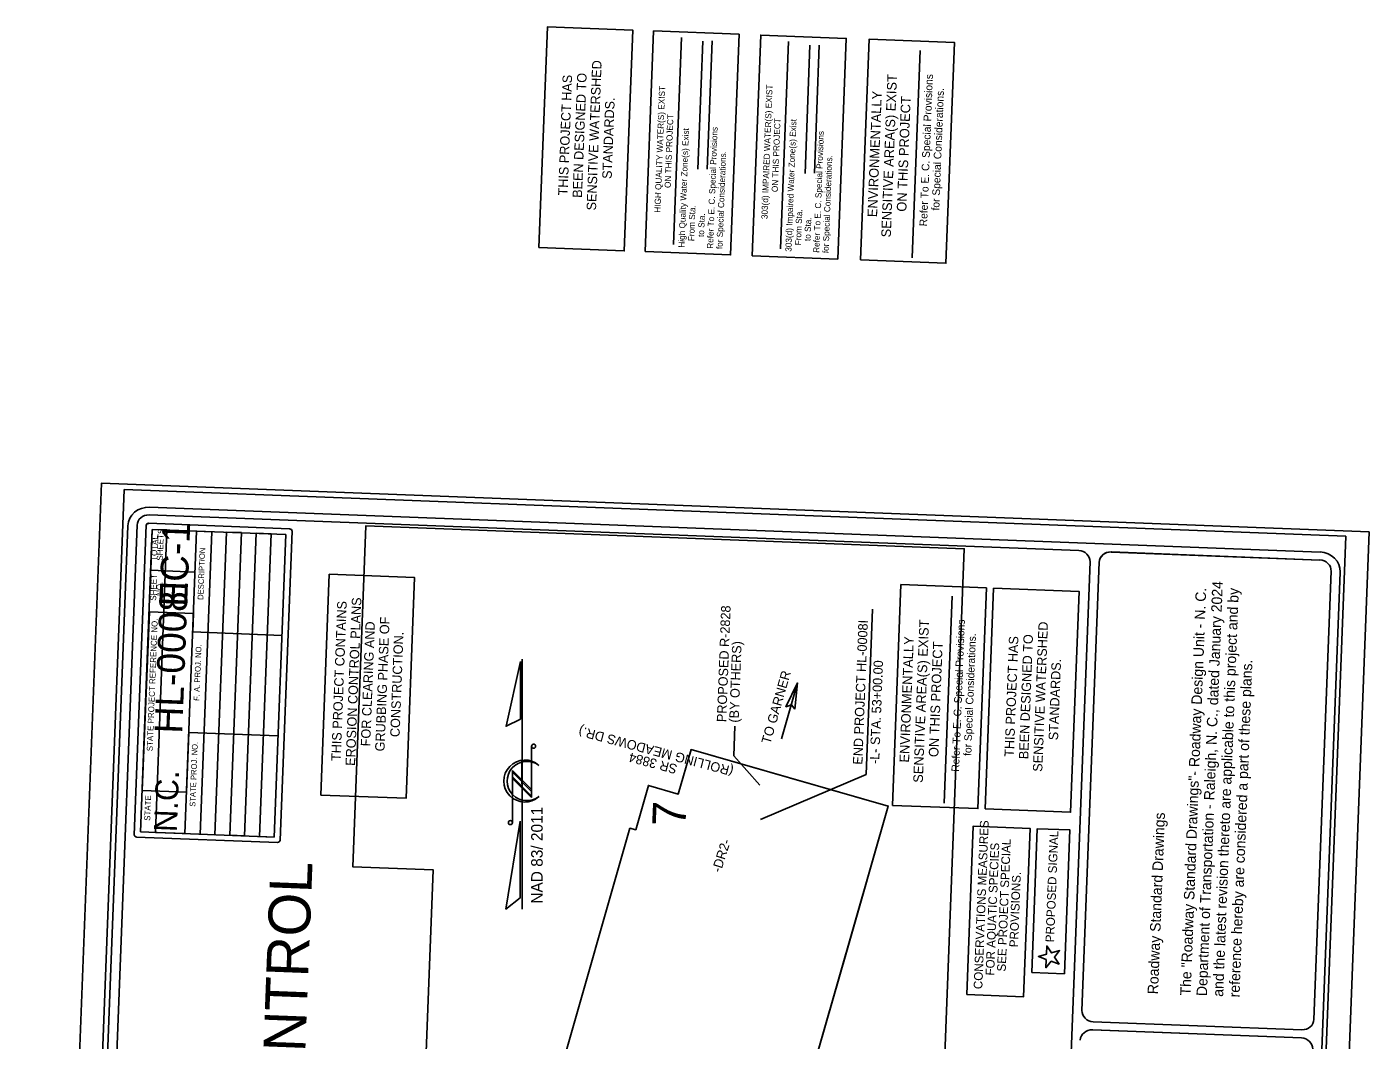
# Model space of a CAD drawing. Extents: x 1654773 to 2116434, y 680831 to 888488.
# Drawn here: x 2094746 to 2100565, y 688306 to 692697 of the extents above; entities that cross this region are included whole.
import ezdxf

# ---------------------------------------------------------------- set-up
doc = ezdxf.new("R2010")
doc.units = 0
for name, color, linetype in [('Default', 7, 'Continuous'), ('EC Title Sheet CELL', 7, 'Continuous'), ('EC Title Sheet Consultant CELL', 7, 'Continuous'), ('Prop DSN Text', 7, 'Continuous'), ('Prop Horizontal Alignment', 7, 'Continuous'), ('Prop RDY Traffic Signal CELL', 7, 'Continuous'), ('Prop Terminator CELL', 7, 'Continuous'), ('Scratch_Level_3', 7, 'Continuous'), ('Sheet Data Field CELL', 7, 'Continuous'), ('Sheet North Arrow CELL', 7, 'Continuous'), ('Sheet Plot Border Inside CELL', 7, 'Continuous'), ('Sheet Plot Border Outside CELL', 7, 'Continuous'), ('Sheet Title CELL', 7, 'Continuous')]:
    doc.layers.add(name, color=color, linetype=linetype)

msp = doc.modelspace()

# ---------------------------------------------------------------- linework, layer by layer
at = {"layer": 'Default'}
msp.add_line((2096893.9, 689316.6), (2096892.4, 689515), dxfattribs=at)
at = {"layer": 'EC Title Sheet CELL'}
for p, q in [((2097655.6, 692079.9), (2097676.9, 692635.1)), ((2097695.7, 692080.9), (2097717, 692636.1)), ((2098119.9, 692062.1), (2098141.2, 692617.3)), ((2098160, 692063.1), (2098181.4, 692618.2)), ((2095069.1, 690719.1), (2095069.1, 690719.1)), ((2095168.6, 690692.8), (2095168.6, 690692.8)), ((2100352.6, 690421), (2095278.4, 690615.8)), ((2095276, 690582.2), (2099306.4, 690427.5)), ((2094948.2, 683360.1), (2095223.7, 690537.4)), ((2095263.2, 690536.9), (2095211.7, 689195.8)), ((2095289.8, 690519), (2095239.5, 689207.9)), ((2095885.3, 690521.8), (2095273.6, 690545.8)), ((2095289.8, 690519), (2095284.1, 690342.6)), ((2095353.6, 690516.7), (2095289.8, 690519)), ((2095868.9, 690496.8), (2095289.8, 690519)), ((2095303.2, 689206.3), (2095353.6, 690516.7)), ((2095481.8, 690511.8), (2095431.5, 689201.4)), ((2095547.5, 690509.3), (2095481.8, 690511.8)), ((2095497.3, 689198.9), (2095547.5, 690509.3)), ((2095611.2, 690506.7), (2095560.9, 689195.5)), ((2095676.9, 690505.1), (2095611.2, 690506.7)), ((2095626.6, 689194), (2095676.9, 690505.1)), ((2095739.6, 690502.8), (2095689.3, 689191.5)), ((2095805.3, 690500.2), (2095739.6, 690502.8)), ((2095754.9, 689189), (2095805.3, 690500.2)), ((2095868.9, 690496.8), (2095818.6, 689185.6)), ((2095843.8, 689172.5), (2095896.1, 690511)), ((2099079.7, 683201.5), (2099355.1, 690378.9)), ((2099320, 688434.4), (2099394.5, 690377.3)), ((2099446.8, 690421.1), (2100351.4, 690386.4)), ((2099448.9, 690422), (2100351.4, 690386.4)), ((2095284.1, 690342.6), (2095475.1, 690334.3)), ((2100400, 690337.9), (2100325.5, 688395.8)), ((2095246.5, 689387.9), (2095277.2, 690162.5)), ((2095277.2, 690162.5), (2095468.2, 690155.1)), ((2095468.2, 690155.1), (2095465.1, 690074.9)), ((2095465.1, 690074.9), (2095852.2, 690060.1)), ((2095448.3, 689639.2), (2095438.5, 689380.6)), ((2095835.4, 689624.3), (2095448.3, 689639.2)), ((2095438.5, 689380.6), (2095246.5, 689387.9)), ((2095221.5, 689186.1), (2095832.3, 689162.6)), ((2095239.5, 689207.9), (2095818.6, 689185.6)), ((2095431.5, 689201.4), (2095303.2, 689206.3)), ((2095560.9, 689195.5), (2095497.3, 689198.9)), ((2095689.3, 689191.5), (2095626.6, 689194)), ((2095818.6, 689185.6), (2095754.9, 689189)), ((2100271.8, 688315.7), (2099365.3, 688350.4)), ((2099367.3, 688350.4), (2100271.8, 688315.7)), ((2099368.7, 688384.9), (2100273.1, 688350.2))]:
    msp.add_line(p, q, dxfattribs=at)
for points in [[(2096965.9, 691740.6), (2097002.6, 692697.2), (2097372.8, 692682.9), (2097336.1, 691726.3)], [(2097426.6, 691722.9), (2097463.4, 692679.5), (2097833.6, 692665.2), (2097796.9, 691708.7)], [(2097891, 691705.1), (2097927.7, 692661.7), (2098298, 692647.4), (2098261.2, 691690.8)], [(2098360.3, 691687), (2098397.1, 692643.7), (2098767.3, 692629.4), (2098730.6, 691672.8)], [(2096020.2, 689368.1), (2096056.9, 690324.7), (2096427.1, 690310.5), (2096390.5, 689353.9)], [(2098499, 689323.2), (2098535.7, 690279.9), (2098906, 690265.6), (2098869.2, 689309)], [(2098900.7, 689307.8), (2098937.4, 690264.4), (2099307.7, 690250.1), (2099270.9, 689293.5)], [(2098117.8, 688054.5), (2097347.7, 688084), (2097057.8, 688167), (2097360.5, 689224.4), (2097385.8, 689217.2), (2097440.8, 689409.5), (2097570.4, 689372.4), (2097625.5, 689564.8), (2098480.1, 689320.1)]]:
    msp.add_lwpolyline(points, close=True, dxfattribs=at)
for points in [[(2097549.3, 691753.4), (2097549.3, 691755.2), (2097583.7, 692651.3)], [(2098013.6, 691735.6), (2098013.7, 691737.3), (2098048.1, 692633.4)], [(2098583.9, 691696.1), (2098584, 691697.8), (2098618.4, 692594)], [(2095184.2, 690535.2), (2094896.9, 683050)], [(2100152.1, 682848.2), (2100439.3, 690334.4)], [(2098722.6, 689332.3), (2098722.6, 689334), (2098757, 690230.2)]]:
    msp.add_lwpolyline(points, dxfattribs=at)
for centre, major_axis, ratio, start_param, end_param in [((2095275.1, 690531.7), (-91, 3.5), 0.923408, 4.712389, 6.283185), ((2095274.3, 690535.5), (-50.5, 1.9), 0.923408, 4.712389, 6.283185), ((2095273.3, 690536.5), (-10.1, 0.4), 0.923408, 4.712389, 6.283185), ((2095274.3, 690535.1), (-11.1, 0.4), 0.923408, 4.712389, 6.283185), ((2095884.9, 690511.5), (-11.1, 0.4), 0.928309, 3.141593, 4.712389), ((2099304.6, 690380.8), (50.5, -1.9), 0.923408, 6.283185, 7.853982), ((2099445.1, 690375), (-50.5, 1.9), 0.923408, 4.712389, 6.283185), ((2099446.3, 690374), (-51.6, 2), 0.923408, 4.712389, 6.283185), ((2099446.3, 690374), (-51.6, 2), 0.923408, 4.712389, 6.283185), ((2100349.6, 690340.3), (50.5, -1.9), 0.923408, 6.283185, 7.853982), ((2100349.6, 690338.4), (-89.9, 3.5), 0.923408, 3.141593, 4.712389), ((2095221.8, 689195.5), (10.1, -0.4), 0.923408, 3.141593, 4.712389), ((2095832.7, 689172.9), (11.1, -0.4), 0.923408, 4.712389, 6.283185), ((2099370.6, 688432.1), (-50.5, 1.9), 0.923408, 6.283185, 7.853982), ((2100275.1, 688397.3), (50.5, -1.9), 0.923408, 4.712389, 6.283185), ((2099363.5, 688303.8), (-50.5, 1.9), 0.923408, 4.712389, 6.283185), ((2100270.1, 688268.6), (-50.5, 1.9), 0.923408, 3.141593, 4.712389)]:
    msp.add_ellipse(centre, major_axis=major_axis, ratio=ratio, start_param=start_param, end_param=end_param, dxfattribs=at)
at = {"layer": 'EC Title Sheet Consultant CELL'}
for points in [[(2098820.5, 688503), (2098848.5, 689232.7), (2099095.1, 689223.3), (2099067.1, 688493.6)], [(2099102.6, 688598.7), (2099126.5, 689222), (2099268, 689216.6), (2099244.1, 688593.2)]]:
    msp.add_lwpolyline(points, close=True, dxfattribs=at)
at = {"layer": 'Prop Horizontal Alignment'}
msp.add_line((2098087.2, 689854), (2098017.9, 689611.8), dxfattribs=at)
at = {"layer": 'Prop RDY Traffic Signal CELL'}
msp.add_lwpolyline([(2099165.6, 688655.5), (2099164.2, 688619.3), (2099186.7, 688647.8), (2099220.9, 688635.2), (2099200.6, 688665.4), (2099223.1, 688693.9), (2099188.1, 688684), (2099167.8, 688714.2), (2099166.4, 688677.9), (2099131.4, 688668), (2099165.6, 688655.5)], dxfattribs=at)
at = {"layer": 'Prop Terminator CELL'}
msp.add_lwpolyline([(2098075.2, 689740.6), (2098087.2, 689854), (2098037.1, 689750.7), (2098060.3, 689759.1)], close=True, dxfattribs=at)
at = {"layer": 'Scratch_Level_3'}
msp.add_lwpolyline([(2096808.4, 683360), (2096881.4, 685262.6), (2096363.6, 685282.4), (2096507.8, 689043.2), (2096159.7, 689056.5), (2096216.4, 690534.7), (2098809.6, 690435.2), (2098650.1, 686277.9), (2099132, 686259.4), (2099018.8, 683308.3), (2099031.1, 683307.9), (2099030, 683278.9)], close=True, dxfattribs=at)
msp.add_lwpolyline([(2098117.8, 688054.5), (2098298.9, 688687.3), (2098480.1, 689320.1), (2098052.8, 689442.4), (2097625.5, 689564.8), (2097570.4, 689372.4), (2097440.8, 689409.5), (2097385.8, 689217.2), (2097360.5, 689224.4), (2097058, 688167.4)], dxfattribs=at)
at = {"layer": 'Sheet Data Field CELL'}
for p, q in [((2098385, 689457.4), (2098412.5, 690173.5)), ((2097811.1, 689537.9), (2097816, 689666.6)), ((2097923.1, 689410.4), (2097811.1, 689537.9)), ((2098385, 689457.4), (2097926.3, 689261.8))]:
    msp.add_line(p, q, dxfattribs=at)
at = {"layer": 'Sheet North Arrow CELL'}
for p, q in [((2096893.2, 688873.5), (2096893.3, 689956.8)), ((2096934.1, 689579.8), (2096934.1, 689357.5)), ((2096934.1, 689392.1), (2096851.3, 689475)), ((2096851.3, 689475), (2096851.3, 689249)), ((2096934.1, 689384), (2096851.3, 689466.8)), ((2096851.3, 689466.8), (2096851.3, 689446.5)), ((2096934.1, 689363.6), (2096851.3, 689446.5)), ((2096851.3, 689446.5), (2096934.1, 689363.6)), ((2096964.8, 689497), (2096965.9, 689496.1)), ((2096934.1, 689357.5), (2096851.3, 689440.3)), ((2096934.1, 689363.6), (2096934.1, 689384))]:
    msp.add_line(p, q, dxfattribs=at)
for points in [[(2096885.8, 689947.3), (2096823.9, 689666), (2096885.8, 689697.3)], [(2096884.4, 689255.1), (2096823.1, 688873.5), (2096884.4, 688921.8)]]:
    msp.add_lwpolyline(points, close=True, dxfattribs=at)
for centre in [(2096942.9, 689579.6), (2096842.4, 689248.6)]:
    msp.add_circle(centre, 8.83, dxfattribs=at)
for centre, radius, start, end in [((2096904.8, 689428.7), 91, 47.83833, 312.39237), ((2096913.6, 689428.7), 85.3, 53.09335, 308.62702)]:
    msp.add_arc(centre, radius, start, end, dxfattribs=at)
at = {"layer": 'Sheet Plot Border Inside CELL'}
msp.add_lwpolyline([(2095168.6, 690692.8), (2094849, 682366.6), (2100144.4, 682163.3), (2100464, 690489.5)], close=True, dxfattribs=at)
at = {"layer": 'Sheet Plot Border Outside CELL'}
msp.add_lwpolyline([(2100242.3, 682094.5), (2100565.2, 690508.2), (2095069.1, 690719.1), (2094746.1, 682305.5)], close=True, dxfattribs=at)
msp.add_lwpolyline([(2100242.3, 682094.5), (2100565.2, 690508.2), (2095069.1, 690719.1), (2094746.1, 682305.5)], close=True, dxfattribs=at)

# ---------------------------------------------------------------- texts
at = {"layer": 'EC Title Sheet CELL'}
for s, height, p in [('SENSITIVE WATERSHED', 40.954, (2097213.3, 691901)), ('THIS PROJECT HAS', 40.954, (2097090.1, 691965.7)), ('BEEN DESIGNED TO ', 40.954, (2097152.5, 691955.5)), ('SENSITIVE AREA(S) EXIST', 41.591, (2098491.4, 691784.3)), ('Refer To E. C. Special Provisions', 33.273, (2098648.8, 691832.2)), ('    HIGH QUALITY WATER(S) EXIST', 26.619, (2097491.2, 691851.6)), ('   303(d) IMPAIRED WATER(S) EXIST', 26.619, (2097955.6, 691833.8)), ('ENVIRONMENTALLY ', 41.591, (2098431.8, 691872)), ('for Special Considerations.', 33.273, (2098701.7, 691900.8)), ('STANDARDS.', 40.95, (2097281.3, 692037.7)), ('ON THIS PROJECT', 41.591, (2098558.7, 691895.6)), ('               ON THIS PROJECT', 26.619, (2097531.5, 691850.1)), ('               ON THIS PROJECT', 26.619, (2097995.8, 691832.3)), ('303(d) Impaired Water Zone(s) Exist', 26.619, (2098060.6, 691722)), ('High Quality Water Zone(s) Exist', 26.619, (2097597, 691739.8)), ('Refer To E. C. Special Provisions', 26.619, (2097720.7, 691735.1)), ('Refer To E. C. Special Provisions', 26.619, (2098181.4, 691717.4)), ('for Special Considerations.', 26.619, (2097761.6, 691733.5)), ('for Special Considerations.', 26.619, (2098221.7, 691715.8)), ('   From Sta.                      ', 26.619, (2097637.9, 691738.3)), ('   From Sta.                      ', 26.619, (2098100.9, 691720.4)), ('     to Sta.', 26.619, (2097679.8, 691736.7)), ('     to Sta.', 26.619, (2098141.2, 691718.9)), ('TOTAL', 25.82, (2095309.8, 690382.7)), ('SHEETS', 25.82, (2095335.2, 690383.6)), ('EC-1', 120.42, (2095440.7, 690182.8)), ('DESCRIPTION', 24.788, (2095510.9, 690213.3)), ('SHEET', 25.82, (2095306.3, 690209.9)), ('HL-0008I', 120.42, (2095419.5, 689632.8)), ('NO.', 25.82, (2095332.4, 690230.5)), ('The "Roadway Standard Drawings"- Roadway Design Unit - N. C.', 45.516, (2099791.2, 688498.5)), ('Department of Transportation - Raleigh, N. C., dated January 2024', 45.516, (2099861.8, 688495.8)), ('and the latest revision thereto are applicable to this project and by', 45.516, (2099932.4, 688493.1)), ('THIS PROJECT CONTAINS', 40.954, (2096106.5, 689514.8)), ('EROSION CONTROL PLANS', 40.954, (2096168.6, 689493.9)), ('STATE PROJECT REFERENCE NO.', 25.82, (2095291.4, 689557.3)), ('FOR CLEARING AND', 40.954, (2096234.6, 689578.4)), ('GRUBBING PHASE OF', 40.954, (2096296.6, 689556.4)), ('SENSITIVE AREA(S) EXIST', 41.591, (2098630.1, 689420.5)), ('Refer To E. C. Special Provisions', 33.273, (2098787.4, 689468.4)), ('SENSITIVE WATERSHED', 40.954, (2099148.1, 689468.2)), ('CONSTRUCTION.', 40.954, (2096361.8, 689618.5)), ('ENVIRONMENTALLY ', 41.591, (2098570.5, 689508.2)), ('ON THIS PROJECT', 41.591, (2098697.3, 689531.8)), ('for Special Considerations.', 33.273, (2098840.4, 689537)), ('THIS PROJECT HAS', 40.954, (2099024.9, 689532.9)), ('BEEN DESIGNED TO ', 40.954, (2099087.4, 689522.7)), ('F. A. PROJ. NO.', 24.788, (2095494.1, 689775.7)), ('STANDARDS.', 40.95, (2099216.2, 689604.9)), ('reference hereby are considered a part of these plans.', 45.516, (2100003.1, 688490.4)), ('STATE PROJ. NO.', 24.788, (2095476.4, 689316.5)), ('N.C.', 99.97, (2095396.3, 689206.5)), ('STATE', 25.82, (2095280.8, 689255.8)), ('Roadway Standard Drawings', 45.516, (2099649.9, 688503.9)), ('HIGHWAY EROSION CONTROL', 181.978, (2095846.2, 685469))]:
    msp.add_text(s, height=height, rotation=87.80201, dxfattribs=at).set_placement(p)
at = {"layer": 'Prop DSN Text'}
for s, p in [('CONSERVATIONS MEASURES ', (2098888, 688526.1)), ('PROPOSED SIGNAL', (2099199.4, 688729.3)), ('FOR AQUATIC SPECIES', (2098939.6, 688585.2)), ('SEE PROJECT SPECIAL ', (2098989.6, 688602.5)), ('PROVISIONS.', (2099043, 688707.7))]:
    msp.add_text(s, height=37.614, rotation=87.80201, dxfattribs=at).set_placement(p)
at = {"layer": 'Sheet Data Field CELL'}
for s, rotation, p in [('PROPOSED R-2828', 87.80201, (2097777.9, 689683.3)), ('END PROJECT HL-0008I', 87.80201, (2098368.2, 689499)), ('(BY OTHERS)', 87.80201, (2097831.6, 689681.2)), ('-L- STA. 53+00.00', 87.80201, (2098441, 689501.9)), ('TO GARNER', 74.0242, (2097969.1, 689586.6)), ('(ROLLING MEADOWS DR.)', 165.16681, (2097812.6, 689489.3)), ('SR 3884', 165.16681, (2097569, 689498.2)), ('-DR2-', 72.40011, (2097753.8, 689029.7))]:
    msp.add_text(s, height=41, rotation=rotation, dxfattribs=at).set_placement(p)
at = {"layer": 'Sheet North Arrow CELL'}
msp.add_text('NAD 83/ 2011', height=50, rotation=89.99831, dxfattribs=at).set_placement((2096982.4, 688897.2))
at = {"layer": 'Sheet Title CELL'}
msp.add_text('7', height=144.6, rotation=87.63475, dxfattribs=at).set_placement((2097601.2, 689229.6))

doc.saveas('drawing.dxf')
